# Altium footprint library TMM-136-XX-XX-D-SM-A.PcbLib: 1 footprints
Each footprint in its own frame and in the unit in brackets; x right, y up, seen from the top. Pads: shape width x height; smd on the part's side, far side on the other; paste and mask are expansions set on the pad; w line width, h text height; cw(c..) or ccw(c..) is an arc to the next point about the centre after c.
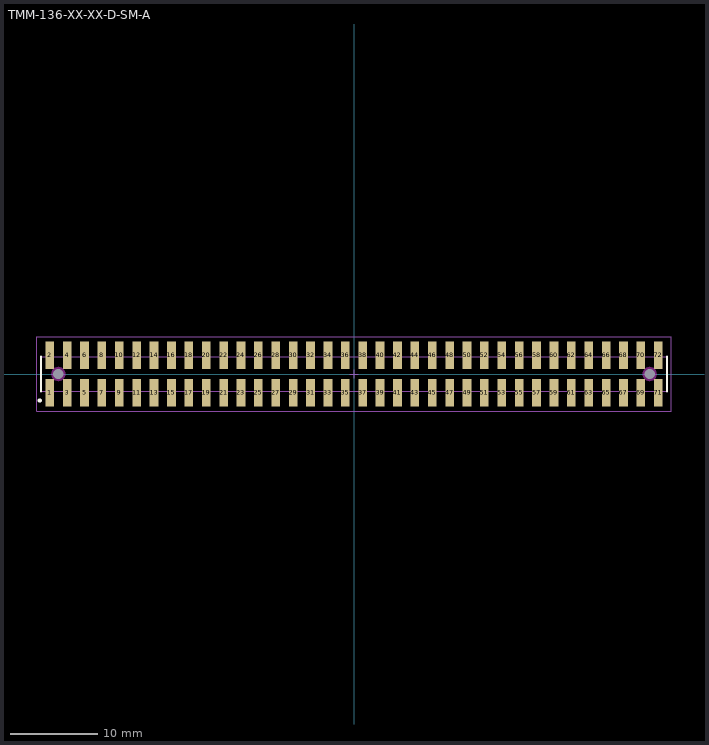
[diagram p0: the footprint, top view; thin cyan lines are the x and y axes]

## TMM-136-XX-XX-D-SM-A [mm] "2.00mm pitch, 72 pin, terminal strip; double row, w/alignment pins, SMT"
height 2.77
pads (74):
  rect 1x3.2 smd mask+0: 1(-35,-2.15) 2(-35,2.15) 3(-33,-2.15) 4(-33,2.15) 5(-31,-2.15) 6(-31,2.15) 7(-29,-2.15) 8(-29,2.15) 9(-27,-2.15) 10(-27,2.15) 11(-25,-2.15) 12(-25,2.15) 13(-23,-2.15) 14(-23,2.15) 15(-21,-2.15) 16(-21,2.15) 17(-19,-2.15) 18(-19,2.15) 19(-17,-2.15) 20(-17,2.15) 21(-15,-2.15) 22(-15,2.15) 23(-13,-2.15) 24(-13,2.15) 25(-11,-2.15) 26(-11,2.15) 27(-9,-2.15) 28(-9,2.15) 29(-7,-2.15) 30(-7,2.15) 31(-5,-2.15) 32(-5,2.15) 33(-3,-2.15) 34(-3,2.15) 35(-1,-2.15) 36(-1,2.15) 37(1,-2.15) 38(1,2.15) 39(3,-2.15) 40(3,2.15) 41(5,-2.15) 42(5,2.15) 43(7,-2.15) 44(7,2.15) 45(9,-2.15) 46(9,2.15) 47(11,-2.15) 48(11,2.15) 49(13,-2.15) 50(13,2.15) 51(15,-2.15) 52(15,2.15) 53(17,-2.15) 54(17,2.15) 55(19,-2.15) 56(19,2.15) 57(21,-2.15) 58(21,2.15) 59(23,-2.15) 60(23,2.15) 61(25,-2.15) 62(25,2.15) 63(27,-2.15) 64(27,2.15) 65(29,-2.15) 66(29,2.15) 67(31,-2.15) 68(31,2.15) 69(33,-2.15) 70(33,2.15) 71(35,-2.15) 72(35,2.15)
  round 1 hole 1.2 unplated mask+0: 73(-34,0) 74(34,0)
Top Overlay:
  circle w0.25: c-36.15,-3.05 r0.125
  lines w0.2: -36,-2 -36,2 ; 36,-2 36,2
Keep-Out Layer:
  pour cut-out: 34.807,0 34.779,0.209 34.699,0.403 34.57,0.571 34.403,0.699 34.209,0.779 34,0.807 33.791,0.779 33.596,0.699 33.429,0.571 33.301,0.403 33.22,0.209 33.193,0 33.22,-0.209 33.301,-0.403 33.429,-0.571 33.596,-0.699 33.791,-0.779 34,-0.807 34.209,-0.779 34.403,-0.699 34.57,-0.571 34.699,-0.403 34.779,-0.209
  pour cut-out: -33.193,0 -33.22,0.209 -33.301,0.403 -33.429,0.571 -33.596,0.699 -33.791,0.779 -34,0.807 -34.209,0.779 -34.403,0.699 -34.57,0.571 -34.699,0.403 -34.779,0.209 -34.807,0 -34.779,-0.209 -34.699,-0.403 -34.57,-0.571 -34.403,-0.699 -34.209,-0.779 -34,-0.807 -33.791,-0.779 -33.596,-0.699 -33.429,-0.571 -33.301,-0.403 -33.22,-0.209
Mechanical 12:
  lines w0.001: -36,-2 -36,2 36,2 36,-2 -36,-2
Mechanical 13:
  lines w0.1: -36,-2 -36,2 36,2 36,-2 -36,-2
  text ".Designator" at -0.127,-0.127 h1.52
Mechanical 15:
  lines w0.05: -0.5,0 0.5,0 ; 0,-0.5 0,0.5 ; -36.5,-4.3 -36.5,4.3 36.5,4.3 36.5,-4.3 -36.5,-4.3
